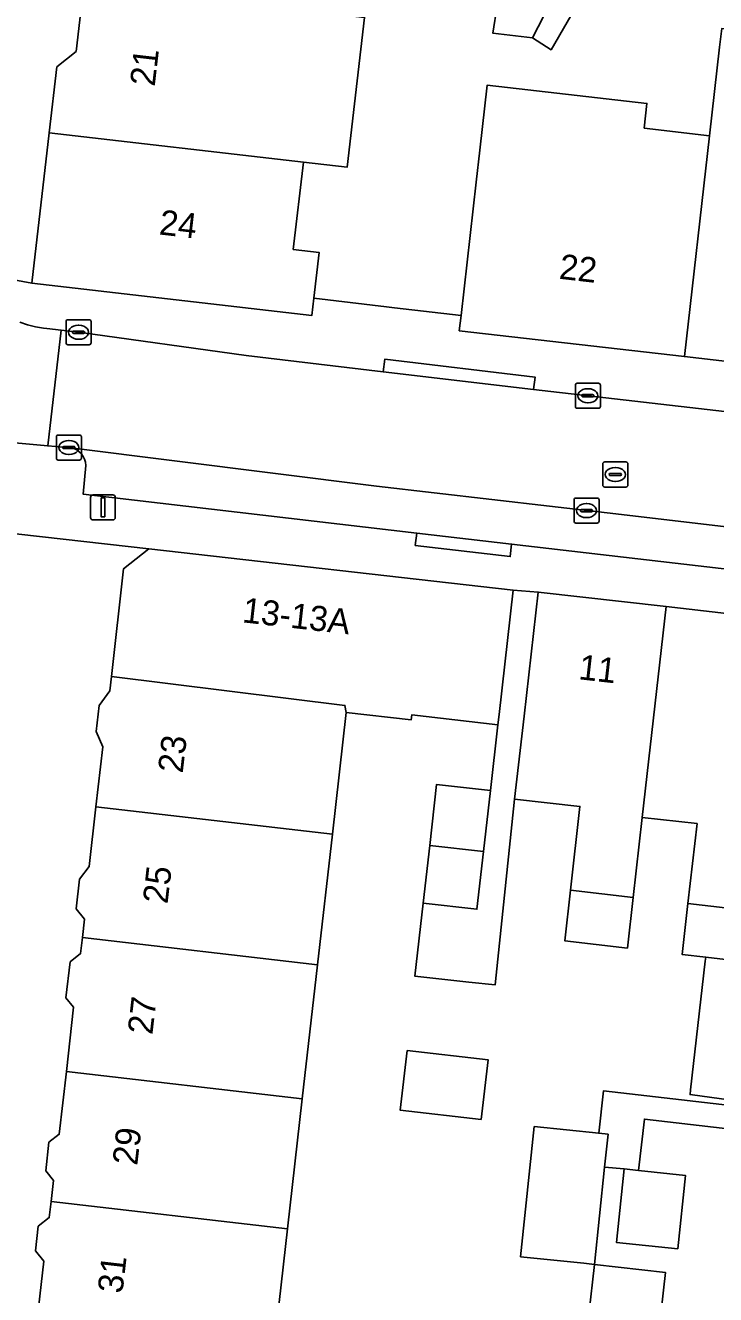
# Model space of a CAD drawing. Extents: x 161692 to 162379, y 380760 to 381678.
# Drawn here: x 162166.2 to 162193.8, y 381104 to 381154.7 of the extents above; entities that cross this region are included whole.
import ezdxf

# ---------------------------------------------------------------- set-up
doc = ezdxf.new("R2010")
doc.units = 0
for name, color, linetype in [('IMGEO_Erf', 7, 'Continuous'), ('IMGEO_Kolk', 7, 'Continuous'), ('IMGEO_Lichtmast', 7, 'Continuous'), ('IMGEO_Muur', 7, 'Continuous'), ('IMGEO_Pand', 7, 'Continuous'), ('IMGEO_Pand_nummerreeks', 7, 'Continuous'), ('IMGEO_Parkeervlak_open', 7, 'Continuous'), ('IMGEO_Rijbaan_lokaal_open', 7, 'Continuous'), ('IMGEO_Rioolput', 7, 'Continuous'), ('IMGEO_Voetpad_open', 7, 'Continuous')]:
    doc.layers.add(name, color=color, linetype=linetype)

msp = doc.modelspace()

# ---------------------------------------------------------------- linework, layer by layer
at = {"layer": 'IMGEO_Erf'}
for points in [[(162190.787, 381159.956), (162187.187, 381153.72), (162186.438, 381154.204), (162184.851, 381154.388), (162185.377, 381157.678)], [(162179.724, 381155.017), (162179.03, 381149.027), (162177.278, 381149.23), (162176.873, 381145.737), (162177.905, 381145.618), (162177.694, 381143.796), (162180.605, 381143.446), (162180.922, 381143.41), (162183.584, 381143.104), (162184.191, 381148.432), (162184.336, 381149.703), (162184.634, 381152.312), (162191.022, 381151.577), (162190.91, 381150.587), (162193.523, 381150.286), (162193.925, 381153.829)], [(162166.578, 381102.496), (162166.896, 381105.29), (162166.565, 381105.706), (162166.677, 381106.69), (162167.112, 381107.036), (162167.185, 381107.675), (162167.28, 381108.514), (162166.974, 381108.899), (162167.104, 381110.044), (162167.513, 381110.369), (162167.798, 381112.871), (162168.09, 381115.443), (162167.784, 381115.826), (162167.947, 381117.253), (162168.366, 381117.586), (162168.439, 381118.231), (162168.522, 381118.962), (162168.195, 381119.373), (162168.33, 381120.56), (162168.711, 381121.076), (162168.982, 381123.456), (162169.255, 381125.857), (162168.987, 381126.473), (162169.106, 381127.513), (162169.533, 381128.091), (162169.598, 381128.663), (162170.088, 381132.972), (162171.096, 381133.774), (162165.058, 381134.446)], [(162194.775, 381111.672), (162192.745, 381111.951), (162192.767, 381112.143), (162193.351, 381117.28), (162193.37, 381117.445), (162192.424, 381117.554), (162192.659, 381119.59), (162193.028, 381122.783), (162190.83, 381123.033), (162190.467, 381119.834), (162190.237, 381117.81), (162187.741, 381118.098), (162187.967, 381120.123), (162188.34, 381123.471), (162185.729, 381123.768), (162184.948, 381116.333), (162183.891, 381116.444), (162181.736, 381116.689), (162182.069, 381119.609), (162182.331, 381121.913), (162182.608, 381124.351), (162184.763, 381124.106), (162185.061, 381126.738), (162181.612, 381127.13), (162181.589, 381126.931), (162178.992, 381127.226), (162178.439, 381122.363), (162177.845, 381117.143), (162177.235, 381111.78), (162176.644, 381106.581), (162176.055, 381101.4)], [(162188.464, 381101.156), (162188.919, 381105.162), (162188.49, 381105.207), (162185.967, 381105.471), (162186.511, 381110.675), (162189.091, 381110.405), (162189.288, 381112.105), (162192.05, 381111.786), (162196.779, 381111.238)], [(162200.24, 381109.895), (162190.919, 381110.973), (162190.682, 381108.92), (162192.559, 381108.723), (162192.252, 381105.788), (162189.798, 381106.045), (162190.105, 381108.98), (162189.326, 381109.057), (162188.919, 381105.162), (162191.769, 381104.838), (162191.313, 381100.832)]]:
    msp.add_lwpolyline(points, dxfattribs=at)
msp.add_lwpolyline([(162184.394, 381110.952), (162181.153, 381111.327), (162181.43, 381113.714), (162184.67, 381113.339)], close=True, dxfattribs=at)
at = {"layer": 'IMGEO_Kolk'}
for p, q in [((162167.787, 381142.001), (162167.787, 381142.853)), ((162167.862, 381142.927), (162168.714, 381142.927)), ((162168.275, 381142.707), (162168.3, 381142.707)), ((162168.788, 381142.853), (162168.788, 381142.001)), ((162168.046, 381142.421), (162168.046, 381142.433)), ((162168.484, 381142.384), (162168.086, 381142.384)), ((162168.089, 381142.47), (162168.487, 381142.47)), ((162168.298, 381142.147), (162168.273, 381142.147)), ((162168.53, 381142.433), (162168.53, 381142.421)), ((162168.714, 381141.927), (162167.862, 381141.927)), ((162188.159, 381139.464), (162188.159, 381140.316)), ((162188.234, 381140.39), (162189.086, 381140.39)), ((162188.647, 381140.17), (162188.672, 381140.17)), ((162189.16, 381140.316), (162189.16, 381139.464)), ((162188.418, 381139.884), (162188.418, 381139.896)), ((162188.856, 381139.847), (162188.458, 381139.847)), ((162188.461, 381139.933), (162188.859, 381139.933)), ((162188.67, 381139.61), (162188.645, 381139.61)), ((162188.902, 381139.896), (162188.902, 381139.884)), ((162189.086, 381139.39), (162188.234, 381139.39)), ((162167.399, 381137.393), (162167.399, 381138.245)), ((162167.474, 381138.319), (162168.326, 381138.319)), ((162167.887, 381138.099), (162167.912, 381138.099)), ((162168.4, 381138.245), (162168.4, 381137.393)), ((162167.658, 381137.813), (162167.658, 381137.825)), ((162168.096, 381137.776), (162167.698, 381137.776)), ((162167.701, 381137.862), (162168.099, 381137.862)), ((162167.91, 381137.539), (162167.885, 381137.539)), ((162168.142, 381137.825), (162168.142, 381137.813)), ((162168.326, 381137.319), (162167.474, 381137.319)), ((162188.103, 381134.872), (162188.103, 381135.724)), ((162188.178, 381135.798), (162189.03, 381135.798)), ((162188.591, 381135.578), (162188.616, 381135.578)), ((162189.104, 381135.724), (162189.104, 381134.872)), ((162188.362, 381135.292), (162188.362, 381135.304)), ((162188.8, 381135.255), (162188.402, 381135.255)), ((162188.405, 381135.341), (162188.803, 381135.341)), ((162188.614, 381135.018), (162188.589, 381135.018)), ((162188.846, 381135.304), (162188.846, 381135.292)), ((162189.03, 381134.798), (162188.178, 381134.798))]:
    msp.add_line(p, q, dxfattribs=at)
for points in [[(162167.787, 381142.001), (162167.787, 381142.853)], [(162167.862, 381142.927), (162168.714, 381142.927)], [(162168.788, 381142.853), (162168.788, 381142.001)], [(162168.714, 381141.927), (162167.862, 381141.927)], [(162188.159, 381139.464), (162188.159, 381140.316)], [(162188.234, 381140.39), (162189.086, 381140.39)], [(162189.16, 381140.316), (162189.16, 381139.464)], [(162189.086, 381139.39), (162188.234, 381139.39)], [(162167.399, 381137.393), (162167.399, 381138.245)], [(162167.474, 381138.319), (162168.326, 381138.319)], [(162168.4, 381138.245), (162168.4, 381137.393)], [(162168.326, 381137.319), (162167.474, 381137.319)], [(162188.103, 381134.872), (162188.103, 381135.724)], [(162188.178, 381135.798), (162189.03, 381135.798)], [(162189.104, 381135.724), (162189.104, 381134.872)], [(162189.03, 381134.798), (162188.178, 381134.798)]]:
    msp.add_lwpolyline(points, dxfattribs=at)
for centre, radius, start, end in [((162167.864, 381142.851), 0.0765, 91.552, 178.448), ((162167.864, 381142.851), 0.0765, 91.552, 178.448), ((162168.712, 381142.851), 0.0765, 1.552, 88.448), ((162168.712, 381142.851), 0.0765, 1.552, 88.448), ((162168.086, 381142.43), 0.0403, 85.8775, 175.7526), ((162168.083, 381142.42), 0.0366, 178.938, 274.7102), ((162168.487, 381142.427), 0.043, 264.8664, 352.4533), ((162168.491, 381142.432), 0.0386, 1.7309, 96.639), ((162167.864, 381142.003), 0.0765, 181.552, 268.448), ((162167.864, 381142.003), 0.0765, 181.552, 268.448), ((162168.712, 381142.003), 0.0765, 271.552, 358.448), ((162168.712, 381142.003), 0.0765, 271.552, 358.448), ((162188.236, 381140.314), 0.0765, 91.552, 178.448), ((162188.236, 381140.314), 0.0765, 91.552, 178.448), ((162189.084, 381140.314), 0.0765, 1.552, 88.448), ((162189.084, 381140.314), 0.0765, 1.552, 88.448), ((162188.458, 381139.893), 0.0403, 85.8775, 175.7526), ((162188.455, 381139.883), 0.0366, 178.938, 274.7102), ((162188.859, 381139.89), 0.043, 264.8664, 352.4533), ((162188.863, 381139.895), 0.0386, 1.7309, 96.639), ((162188.236, 381139.466), 0.0765, 181.552, 268.448), ((162188.236, 381139.466), 0.0765, 181.552, 268.448), ((162189.084, 381139.466), 0.0765, 271.552, 358.448), ((162189.084, 381139.466), 0.0765, 271.552, 358.448), ((162167.476, 381138.243), 0.0765, 91.552, 178.448), ((162167.476, 381138.243), 0.0765, 91.552, 178.448), ((162168.324, 381138.243), 0.0765, 1.552, 88.448), ((162168.324, 381138.243), 0.0765, 1.552, 88.448), ((162167.698, 381137.822), 0.0403, 85.8775, 175.7526), ((162167.695, 381137.812), 0.0366, 178.938, 274.7102), ((162168.099, 381137.819), 0.043, 264.8664, 352.4533), ((162168.103, 381137.824), 0.0386, 1.7309, 96.639), ((162167.476, 381137.395), 0.0765, 181.552, 268.448), ((162167.476, 381137.395), 0.0765, 181.552, 268.448), ((162168.324, 381137.395), 0.0765, 271.552, 358.448), ((162168.324, 381137.395), 0.0765, 271.552, 358.448), ((162188.18, 381135.722), 0.0765, 91.552, 178.448), ((162188.18, 381135.722), 0.0765, 91.552, 178.448), ((162189.028, 381135.722), 0.0765, 1.552, 88.448), ((162189.028, 381135.722), 0.0765, 1.552, 88.448), ((162188.402, 381135.301), 0.0403, 85.8775, 175.7526), ((162188.399, 381135.291), 0.0366, 178.938, 274.7102), ((162188.803, 381135.298), 0.043, 264.8664, 352.4533), ((162188.807, 381135.303), 0.0386, 1.7309, 96.639), ((162188.18, 381134.874), 0.0765, 181.552, 268.448), ((162188.18, 381134.874), 0.0765, 181.552, 268.448), ((162189.028, 381134.874), 0.0765, 271.552, 358.448), ((162189.028, 381134.874), 0.0765, 271.552, 358.448)]:
    msp.add_arc(centre, radius, start, end, dxfattribs=at)
for centre, major_axis, ratio, start_param, end_param in [((162168.274, 381142.427), (-0.387, 0.002), 0.722429, 4.712389, 7.853982), ((162168.299, 381142.427), (-0.39, 0.002), 0.717154, 1.570796, 4.712389), ((162188.646, 381139.89), (-0.387, 0.002), 0.722429, 4.712389, 7.853982), ((162188.671, 381139.89), (-0.39, 0.002), 0.717154, 1.570796, 4.712389), ((162167.886, 381137.819), (-0.387, 0.002), 0.722429, 4.712389, 7.853982), ((162167.911, 381137.819), (-0.39, 0.002), 0.717154, 1.570796, 4.712389), ((162188.59, 381135.298), (-0.387, 0.002), 0.722429, 4.712389, 7.853982), ((162188.615, 381135.298), (-0.39, 0.002), 0.717154, 1.570796, 4.712389)]:
    msp.add_ellipse(centre, major_axis=major_axis, ratio=ratio, start_param=start_param, end_param=end_param, dxfattribs=at)
at = {"layer": 'IMGEO_Lichtmast'}
for p, q in [((162168.765, 381135.027), (162168.765, 381135.827)), ((162168.765, 381135.827), (162168.765, 381135.027)), ((162168.865, 381135.927), (162169.655, 381135.927)), ((162169.655, 381135.927), (162168.865, 381135.927)), ((162169.755, 381135.827), (162169.755, 381135.027)), ((162169.755, 381135.027), (162169.755, 381135.827)), ((162169.655, 381134.927), (162168.865, 381134.927)), ((162168.865, 381134.927), (162169.655, 381134.927))]:
    msp.add_line(p, q, dxfattribs=at)
msp.add_lwpolyline([(162169.185, 381135.802), (162169.335, 381135.802), (162169.335, 381135.052), (162169.185, 381135.052), (162169.185, 381135.802)], dxfattribs=at)
for centre, start, end in [((162168.865, 381135.827), 90, 180), ((162168.865, 381135.827), 90, 180), ((162169.655, 381135.827), 0, 90), ((162169.655, 381135.827), 360, 90), ((162168.865, 381135.027), 180, 270), ((162168.865, 381135.027), 180, 270), ((162169.655, 381135.027), 270, 0), ((162169.655, 381135.027), 270, 0)]:
    msp.add_arc(centre, 0.1, start, end, dxfattribs=at)
at = {"layer": 'IMGEO_Muur'}
msp.add_lwpolyline([(162177.694, 381143.796), (162180.605, 381143.446)], dxfattribs=at)
at = {"layer": 'IMGEO_Pand'}
for points in [[(162188.067, 381157.367), (162185.377, 381157.678), (162184.851, 381154.388), (162186.438, 381154.204)], [(162167.107, 381150.404), (162177.278, 381149.23), (162179.03, 381149.027), (162179.724, 381155.017), (162168.502, 381156.312), (162168.194, 381153.652), (162167.412, 381153.033)], [(162199.62, 381153.925), (162194.01, 381154.57), (162193.985, 381154.352), (162193.925, 381153.829), (162193.523, 381150.286), (162192.52, 381141.456), (162198.134, 381140.811), (162199.583, 381153.573), (162199.597, 381153.707)], [(162193.523, 381150.286), (162190.91, 381150.587), (162191.022, 381151.577), (162184.634, 381152.312), (162184.336, 381149.703), (162184.191, 381148.432), (162183.584, 381143.104), (162183.513, 381142.49), (162192.52, 381141.456)], [(162167.107, 381150.404), (162166.411, 381144.391), (162177.613, 381143.094), (162177.694, 381143.796), (162177.905, 381145.618), (162176.873, 381145.737), (162177.278, 381149.23)], [(162185.673, 381132.116), (162171.096, 381133.774), (162170.088, 381132.972), (162169.598, 381128.663), (162178.939, 381127.511), (162178.992, 381127.226), (162181.589, 381126.931), (162181.612, 381127.13), (162185.061, 381126.738), (162185.108, 381127.149)], [(162190.83, 381123.033), (162191.795, 381131.459), (162186.67, 381132.042), (162186.105, 381127.075), (162185.729, 381123.768), (162188.34, 381123.471), (162187.967, 381120.123), (162190.467, 381119.834)], [(162196.958, 381130.871), (162191.795, 381131.459), (162190.83, 381123.033), (162193.028, 381122.783), (162192.659, 381119.59), (162195.636, 381119.246), (162196, 381122.445)], [(162178.439, 381122.363), (162178.992, 381127.226), (162178.939, 381127.511), (162169.598, 381128.663), (162169.533, 381128.091), (162169.106, 381127.513), (162168.987, 381126.473), (162169.255, 381125.857), (162168.982, 381123.456)], [(162182.331, 381121.913), (162184.485, 381121.664), (162184.763, 381124.106), (162182.608, 381124.351)], [(162168.439, 381118.231), (162177.845, 381117.143), (162178.439, 381122.363), (162168.982, 381123.456), (162168.711, 381121.076), (162168.33, 381120.56), (162168.195, 381119.373), (162168.522, 381118.962)], [(162184.485, 381121.664), (162182.331, 381121.913), (162182.069, 381119.609), (162184.223, 381119.364)], [(162190.467, 381119.834), (162187.967, 381120.123), (162187.741, 381118.098), (162190.237, 381117.81)], [(162195.636, 381119.246), (162192.659, 381119.59), (162192.424, 381117.554), (162193.37, 381117.445), (162195.404, 381117.21)], [(162177.235, 381111.78), (162177.845, 381117.143), (162168.439, 381118.231), (162168.366, 381117.586), (162167.947, 381117.253), (162167.784, 381115.826), (162168.09, 381115.443), (162167.798, 381112.871)], [(162195.404, 381117.21), (162193.37, 381117.445), (162193.351, 381117.28), (162192.767, 381112.143), (162192.745, 381111.951), (162194.775, 381111.672), (162195.381, 381117.001)], [(162184.394, 381110.952), (162184.67, 381113.339), (162181.43, 381113.714), (162181.153, 381111.327)], [(162177.235, 381111.78), (162167.798, 381112.871), (162167.513, 381110.369), (162167.104, 381110.044), (162166.974, 381108.899), (162167.28, 381108.514), (162167.185, 381107.675), (162176.644, 381106.581)], [(162189.326, 381109.057), (162189.463, 381110.366), (162189.091, 381110.405), (162186.511, 381110.675), (162185.967, 381105.471), (162188.49, 381105.207), (162188.919, 381105.162)], [(162190.682, 381108.92), (162190.105, 381108.98), (162189.798, 381106.045), (162192.252, 381105.788), (162192.559, 381108.723)], [(162176.055, 381101.4), (162176.644, 381106.581), (162167.185, 381107.675), (162167.112, 381107.036), (162166.677, 381106.69), (162166.565, 381105.706), (162166.896, 381105.29), (162166.578, 381102.496)], [(162188.919, 381105.162), (162188.464, 381101.156), (162189.767, 381101.008), (162191.313, 381100.832), (162191.769, 381104.838)]]:
    msp.add_lwpolyline(points, close=True, dxfattribs=at)
at = {"layer": 'IMGEO_Parkeervlak_open'}
for points in [[(162219.35, 381131.833), (162212.969, 381132.576), (162202.92, 381133.625), (162201.233, 381133.817), (162189.43, 381135.203), (162180.206, 381136.281), (162167.974, 381137.811)], [(162168.578, 381137.101), (162168.467, 381135.958), (162181.815, 381134.401), (162185.609, 381133.958), (162199.956, 381132.285), (162212.536, 381130.919), (162218.69, 381130.202), (162218.831, 381131.407)]]:
    msp.add_lwpolyline(points, dxfattribs=at)
msp.add_arc((162167.848, 381137.092), 0.73, 0.7176, 80.0583, dxfattribs=at)
at = {"layer": 'IMGEO_Rijbaan_lokaal_open'}
for points in [[(162167.592, 381142.51), (162167.021, 381142.583), (162166.888, 381142.595), (162166.563, 381142.646), (162166.243, 381142.725), (162165.932, 381142.833)], [(162165.142, 381138.059), (162167.053, 381137.885), (162167.592, 381142.51)]]:
    msp.add_lwpolyline(points, dxfattribs=at)
msp.add_lwpolyline([(162167.592, 381142.51), (162167.053, 381137.885), (162167.974, 381137.811), (162180.206, 381136.281), (162189.43, 381135.203), (162201.233, 381133.817), (162202.92, 381133.625), (162212.969, 381132.576), (162219.35, 381131.833), (162219.754, 381131.77), (162220.241, 381136.371), (162217.018, 381136.75), (162203.646, 381138.166), (162200.716, 381138.494), (162186.489, 381140.14), (162180.474, 381140.85), (162174.995, 381141.497), (162168.285, 381142.426)], close=True, dxfattribs=at)
at = {"layer": 'IMGEO_Rioolput'}
for p, q in [((162189.255, 381136.315), (162189.255, 381137.167)), ((162189.33, 381137.241), (162190.182, 381137.241)), ((162190.256, 381137.167), (162190.256, 381136.315)), ((162189.514, 381136.735), (162189.514, 381136.747)), ((162189.952, 381136.698), (162189.554, 381136.698)), ((162189.557, 381136.784), (162189.955, 381136.784)), ((162189.743, 381137.021), (162189.768, 381137.021)), ((162189.998, 381136.747), (162189.998, 381136.735)), ((162190.182, 381136.241), (162189.33, 381136.241)), ((162189.766, 381136.461), (162189.741, 381136.461))]:
    msp.add_line(p, q, dxfattribs=at)
for points in [[(162189.255, 381136.315), (162189.255, 381137.167)], [(162189.33, 381137.241), (162190.182, 381137.241)], [(162190.256, 381137.167), (162190.256, 381136.315)], [(162190.182, 381136.241), (162189.33, 381136.241)]]:
    msp.add_lwpolyline(points, dxfattribs=at)
for centre, radius, start, end in [((162189.332, 381137.165), 0.0765, 91.552, 178.448), ((162189.332, 381137.165), 0.0765, 91.552, 178.448), ((162190.18, 381137.165), 0.0765, 1.552, 88.448), ((162190.18, 381137.165), 0.0765, 1.552, 88.448), ((162189.554, 381136.744), 0.0403, 85.8775, 175.7526), ((162189.551, 381136.734), 0.0366, 178.938, 274.7102), ((162189.955, 381136.741), 0.043, 264.8664, 352.4533), ((162189.959, 381136.746), 0.0386, 1.7309, 96.639), ((162189.332, 381136.317), 0.0765, 181.552, 268.448), ((162189.332, 381136.317), 0.0765, 181.552, 268.448), ((162190.18, 381136.317), 0.0765, 271.552, 358.448), ((162190.18, 381136.317), 0.0765, 271.552, 358.448)]:
    msp.add_arc(centre, radius, start, end, dxfattribs=at)
for centre, major_axis, ratio, start_param, end_param in [((162189.742, 381136.741), (-0.387, 0.002), 0.722429, 4.712389, 7.853982), ((162189.767, 381136.741), (-0.39, 0.002), 0.717154, 1.570796, 4.712389)]:
    msp.add_ellipse(centre, major_axis=major_axis, ratio=ratio, start_param=start_param, end_param=end_param, dxfattribs=at)
at = {"layer": 'IMGEO_Voetpad_open'}
for points in [[(162165.836, 381166.11), (162163.848, 381148.312), (162163.756, 381147.701), (162163.71, 381147.125), (162163.647, 381146.802), (162163.613, 381146.474), (162163.608, 381146.145), (162163.633, 381145.816), (162163.687, 381145.491), (162163.769, 381145.173), (162163.88, 381144.862), (162166.411, 381144.391), (162167.107, 381150.404), (162167.412, 381153.033), (162168.194, 381153.652), (162168.502, 381156.312)], [(162188.067, 381157.367), (162186.438, 381154.204), (162187.187, 381153.72), (162190.787, 381159.956)], [(162198.134, 381140.811), (162192.52, 381141.456), (162183.513, 381142.49), (162183.584, 381143.104), (162180.922, 381143.41), (162180.605, 381143.446), (162177.694, 381143.796), (162177.613, 381143.094), (162166.411, 381144.391), (162163.88, 381144.862)], [(162165.932, 381142.833), (162166.243, 381142.725), (162166.563, 381142.646), (162166.888, 381142.595), (162167.021, 381142.583), (162167.592, 381142.51), (162168.285, 381142.426), (162174.995, 381141.497), (162180.474, 381140.85), (162180.534, 381141.346), (162186.549, 381140.636), (162186.489, 381140.14), (162200.716, 381138.494)], [(162167.974, 381137.811), (162167.053, 381137.885), (162165.142, 381138.059)], [(162218.831, 381131.407), (162218.69, 381130.202), (162212.536, 381130.919), (162199.956, 381132.285), (162185.609, 381133.958), (162185.55, 381133.463), (162181.756, 381133.905), (162181.815, 381134.401), (162168.467, 381135.958), (162168.578, 381137.101)], [(162160.751, 381134.327), (162165.058, 381134.446), (162171.096, 381133.774), (162185.673, 381132.116), (162186.67, 381132.042), (162191.795, 381131.459), (162196.958, 381130.871), (162202.113, 381130.285), (162202.676, 381130.218), (162206.35, 381129.78), (162219.154, 381128.335), (162223.239, 381127.491)]]:
    msp.add_lwpolyline(points, dxfattribs=at)
for points in [[(162180.474, 381140.85), (162186.489, 381140.14), (162186.549, 381140.636), (162180.534, 381141.346)], [(162181.815, 381134.401), (162181.756, 381133.905), (162185.55, 381133.463), (162185.609, 381133.958)], [(162186.105, 381127.075), (162186.67, 381132.042), (162185.673, 381132.116), (162185.108, 381127.149), (162185.061, 381126.738), (162184.763, 381124.106), (162184.485, 381121.664), (162184.223, 381119.364), (162182.069, 381119.609), (162181.736, 381116.689), (162183.891, 381116.444), (162184.948, 381116.333), (162185.729, 381123.768)], [(162202.676, 381130.218), (162202.113, 381130.285), (162201.548, 381125.318), (162201.154, 381121.859), (162200.503, 381121.933), (162199.23, 381110.954), (162196.779, 381111.238), (162192.05, 381111.786), (162189.288, 381112.105), (162189.091, 381110.405), (162189.463, 381110.366), (162189.326, 381109.057), (162190.105, 381108.98), (162190.682, 381108.92), (162190.919, 381110.973), (162200.24, 381109.895), (162200.348, 381110.824)]]:
    msp.add_lwpolyline(points, close=True, dxfattribs=at)
msp.add_arc((162167.848, 381137.092), 0.73, 0.7176, 80.0583, dxfattribs=at)

# ---------------------------------------------------------------- texts
at = {"layer": 'IMGEO_Pand_nummerreeks'}
for s, rotation, p in [('21', 83.3996, (162171.331, 381152.232)), ('24', 353.3955, (162171.481, 381146.341)), ('22', 353.4511, (162187.48, 381144.57)), ('13-13A', 353.5084, (162174.807, 381130.836)), ('11', 353.5092, (162188.256, 381128.56)), ('23', 83.39, (162172.45, 381124.779)), ('25', 83.39, (162171.844, 381119.551)), ('27', 83.39, (162171.238, 381114.323)), ('29', 83.39, (162170.632, 381109.095)), ('31', 83.39, (162170.039, 381103.98))]:
    msp.add_text(s, height=1, rotation=rotation, dxfattribs=at).set_placement(p)

doc.saveas('drawing.dxf')
